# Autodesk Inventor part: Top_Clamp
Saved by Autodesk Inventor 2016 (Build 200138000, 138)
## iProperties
Created: 2016-03
Part Number: Top_Clamp
Material: Generic
Document SubType Name: Modeling
Designer: bongo_000
Density: 1 g/cm^3
Appearance: Default
Author: bongo_000
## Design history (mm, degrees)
feature "SOLID1"
body "Solid1"
